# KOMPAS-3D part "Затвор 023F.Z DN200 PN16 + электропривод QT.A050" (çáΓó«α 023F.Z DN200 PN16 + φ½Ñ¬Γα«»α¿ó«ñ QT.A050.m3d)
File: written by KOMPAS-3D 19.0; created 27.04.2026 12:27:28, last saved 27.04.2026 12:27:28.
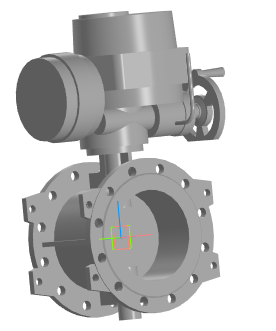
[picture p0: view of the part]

Document properties: Полное имя файла: Затвор 023F.Z DN200 PN16 + электропривод QT.A050.a3d

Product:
- Part/product: Затвор 023F.Z DN200 PN16 + электропривод QT.A050
    Масса: 155.074

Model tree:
1. Операция без истории:1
